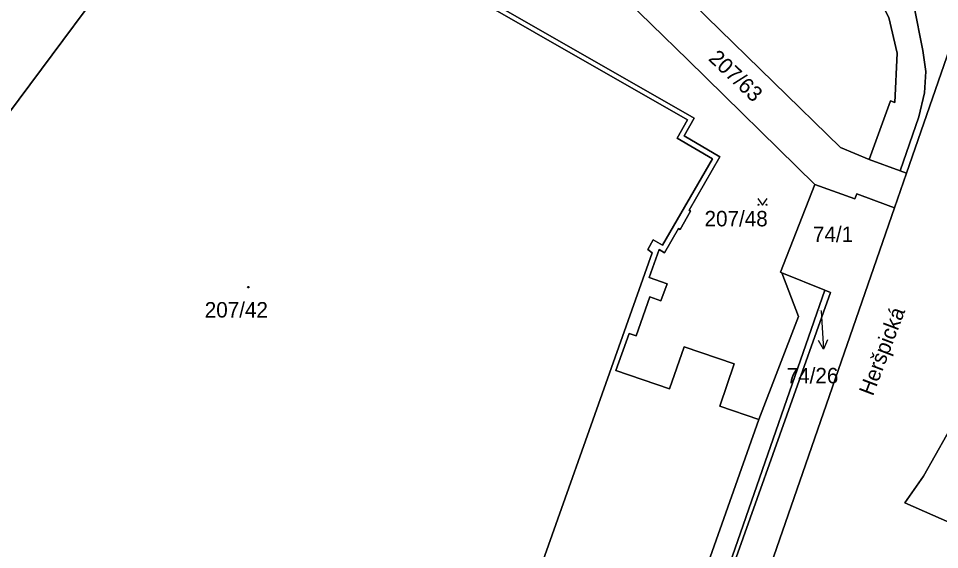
# Model space of a CAD drawing. Extents: x -598934 to -598196, y -1162208 to -1161502.
# Drawn here: x -598686.2 to -598584.8, y -1162112 to -1162053.5 of the extents above; entities that cross this region are included whole.
import ezdxf

# ---------------------------------------------------------------- set-up
doc = ezdxf.new("R2010")
doc.units = 0
for name, color, linetype in [('KN_KULTURY', 7, 'Continuous'), ('KN_PARC_CIS_POM', 7, 'Continuous'), ('KN_PARC_CIS_POZ', 7, 'Continuous'), ('KN_PARC_CIS_STAV', 7, 'Continuous'), ('KN_PARC_PLOCHA', 7, 'Continuous'), ('KN_ULICE', 7, 'Continuous'), ('PARC_C_SIPKA', 7, 'Continuous'), ('parcely_l', 7, 'Continuous')]:
    doc.layers.add(name, color=color, linetype=linetype)

msp = doc.modelspace()

# ---------------------------------------------------------------- linework, layer by layer
at = {"layer": 'KN_KULTURY'}
msp.add_lwpolyline([(-598604.79, -1162073.32), (-598604.29, -1162074.07), (-598603.79, -1162073.32)], dxfattribs=at)
for centre, radius in [((-598604.74, -1162074.02), 0.05), ((-598603.84, -1162074.02), 0.05), ((-598660.89, -1162083.09), 0.09), ((-598660.89, -1162083.09), 0.0398)]:
    msp.add_circle(centre, radius, dxfattribs=at)
at = {"layer": 'KN_PARC_PLOCHA'}
for points in [[(-598693.35, -1161970.89), (-598667.16, -1161993.18), (-598644.52, -1162009.55), (-598619.13, -1162024.88), (-598591.47, -1162039.7), (-598579.44, -1162044.4), (-598582.71, -1162054.06), (-598588.43, -1162070.55), (-598589.13, -1162070.29), (-598587.08, -1162064.36), (-598586.45, -1162061.72), (-598586.32, -1162059.38), (-598586.65, -1162057.07), (-598587.65, -1162052.06), (-598590.3, -1162047.38), (-598592.24, -1162045.35), (-598595.98, -1162042.57), (-598613.53, -1162032.97), (-598652.95, -1162008.48), (-598673.9, -1161993.31), (-598697.93, -1161974.03)], [(-598620.52, -1162050.28), (-598612.52, -1162058.09), (-598598.54, -1162071.79), (-598602.32, -1162081.45), (-598602.15, -1162081.52), (-598600.34, -1162086.32), (-598604.68, -1162097.65), (-598608.99, -1162096.19), (-598607.4, -1162091.53), (-598612.92, -1162089.65), (-598614.51, -1162094.26), (-598620.42, -1162092.27), (-598618.96, -1162088.18), (-598618.19, -1162088.45), (-598616.68, -1162084.17), (-598615.47, -1162084.6), (-598614.79, -1162082.74), (-598616.76, -1162082.02), (-598615.68, -1162078.96), (-598615.09, -1162079.3), (-598613.55, -1162076.63), (-598613.37, -1162076.73), (-598612.21, -1162074.73), (-598612.38, -1162074.63), (-598608.97, -1162068.74), (-598612.93, -1162066.44), (-598611.83, -1162064.5), (-598663.62, -1162034.85)], [(-598663.62, -1162034.85), (-598611.83, -1162064.5), (-598612.93, -1162066.44), (-598608.97, -1162068.74), (-598612.38, -1162074.63), (-598612.21, -1162074.73), (-598613.37, -1162076.73), (-598613.55, -1162076.63), (-598615.09, -1162079.3), (-598615.68, -1162078.96), (-598616.76, -1162082.02), (-598614.79, -1162082.74), (-598615.47, -1162084.6), (-598616.68, -1162084.17), (-598618.19, -1162088.45), (-598618.96, -1162088.18), (-598620.42, -1162092.27), (-598614.51, -1162094.26), (-598612.92, -1162089.65), (-598607.4, -1162091.53), (-598608.99, -1162096.19), (-598604.68, -1162097.65), (-598635.66, -1162185.2)], [(-598625.22, -1162038.92), (-598595.72, -1162067.74), (-598592.55, -1162069.05), (-598589.13, -1162070.29), (-598588.43, -1162070.55), (-598589.75, -1162074.37), (-598590.45, -1162074.11), (-598593.91, -1162072.84), (-598594.12, -1162073.38), (-598598.54, -1162071.79), (-598612.52, -1162058.09), (-598620.52, -1162050.28)], [(-598564.74, -1162050.65), (-598555.77, -1162053.54), (-598559.33, -1162063.57), (-598566.94, -1162060.47), (-598582.73, -1162097.08), (-598586.56, -1162103.9), (-598588.64, -1162106.82), (-598577.56, -1162111.7), (-598576.38, -1162112.22), (-598601.97, -1162185.82), (-598610.3, -1162192.29), (-598613.3, -1162200.15), (-598620.21, -1162196.02), (-598622.04, -1162194.78), (-598629.75, -1162189.23), (-598624.36, -1162173.57), (-598616.39, -1162151.12), (-598609.23, -1162130.49), (-598607.47, -1162125.48), (-598600.18, -1162104.44), (-598589.75, -1162074.37), (-598588.43, -1162070.55), (-598582.71, -1162054.06), (-598579.44, -1162044.4)], [(-598587.65, -1162052.06), (-598586.65, -1162057.07), (-598586.32, -1162059.38), (-598586.45, -1162061.72), (-598587.08, -1162064.36), (-598589.13, -1162070.29), (-598592.55, -1162069.05), (-598590.2, -1162062.59), (-598589.71, -1162062.79), (-598589.48, -1162057.35), (-598590.4, -1162053.41)]]:
    msp.add_lwpolyline(points, dxfattribs=at)
for points in [[(-598592.55, -1162069.05), (-598595.72, -1162067.74), (-598625.22, -1162038.92), (-598640.86, -1162023.52), (-598641.37, -1162022.35), (-598641.1, -1162021.73), (-598640.52, -1162021.18), (-598639.48, -1162020.74), (-598635.86, -1162023.09), (-598611.07, -1162037.77), (-598597.42, -1162045.2), (-598594.15, -1162047.66), (-598591.98, -1162050.31), (-598590.4, -1162053.41), (-598589.48, -1162057.35), (-598589.71, -1162062.79), (-598590.2, -1162062.59)], [(-598668.55, -1162035.34), (-598674.02, -1162044.9), (-598673, -1162045.47), (-598673.6, -1162046.51), (-598674.03, -1162046.15), (-598710.29, -1162094.83), (-598710.79, -1162094.46), (-598717.77, -1162103.75), (-598683.27, -1162115.94), (-598682.6, -1162114.05), (-598663.19, -1162120.99), (-598663.85, -1162122.86), (-598634.84, -1162133.15), (-598632.69, -1162127.23), (-598633.35, -1162126.99), (-598616.44, -1162079.32), (-598616.93, -1162078.93), (-598616.33, -1162077.89), (-598615.31, -1162078.48), (-598609.79, -1162068.96), (-598613.68, -1162066.69), (-598612.54, -1162064.68), (-598663.42, -1162035.55), (-598664.65, -1162037.57)], [(-598668.55, -1162035.34), (-598664.65, -1162037.57), (-598663.42, -1162035.55), (-598612.54, -1162064.68), (-598613.68, -1162066.69), (-598609.79, -1162068.96), (-598615.31, -1162078.48), (-598616.33, -1162077.89), (-598616.93, -1162078.93), (-598616.44, -1162079.32), (-598633.35, -1162126.99), (-598632.69, -1162127.23), (-598634.84, -1162133.15), (-598663.85, -1162122.86), (-598663.19, -1162120.99), (-598682.6, -1162114.05), (-598683.27, -1162115.94), (-598717.77, -1162103.75), (-598710.79, -1162094.46), (-598710.29, -1162094.83), (-598674.03, -1162046.15), (-598673.6, -1162046.51), (-598673, -1162045.47), (-598674.02, -1162044.9)], [(-598559.33, -1162063.57), (-598566.09, -1162082.63), (-598569.46, -1162092.03), (-598577.56, -1162111.7), (-598588.64, -1162106.82), (-598586.56, -1162103.9), (-598582.73, -1162097.08), (-598566.94, -1162060.47)], [(-598589.75, -1162074.37), (-598600.18, -1162104.44), (-598607.47, -1162125.48), (-598611.23, -1162124.16), (-598596.81, -1162083.67), (-598597.43, -1162083.42), (-598602.15, -1162081.52), (-598602.32, -1162081.45), (-598598.54, -1162071.79), (-598594.12, -1162073.38), (-598593.91, -1162072.84), (-598590.45, -1162074.11)], [(-598597.43, -1162083.42), (-598597.71, -1162084.28), (-598607.02, -1162110.95), (-598611.57, -1162124.04), (-598620.68, -1162150.69), (-598631.21, -1162180.12), (-598633.8, -1162185.51), (-598635.66, -1162185.2), (-598604.68, -1162097.65), (-598600.34, -1162086.32), (-598602.15, -1162081.52)], [(-598611.23, -1162124.16), (-598611.57, -1162124.04), (-598607.02, -1162110.95), (-598597.71, -1162084.28), (-598597.43, -1162083.42), (-598596.81, -1162083.67)]]:
    msp.add_lwpolyline(points, close=True, dxfattribs=at)
at = {"layer": 'PARC_C_SIPKA'}
for points in [[(-598597.85, -1162085.7), (-598597.77, -1162086.94), (-598597.58, -1162089.93)], [(-598597.15, -1162088.9), (-598597.58, -1162089.93), (-598598.14, -1162088.97)]]:
    msp.add_lwpolyline(points, dxfattribs=at)
at = {"layer": 'parcely_l'}
for points in [[(-598722.71, -1161953.41), (-598697.93, -1161974.03), (-598673.9, -1161993.31), (-598652.95, -1162008.48), (-598613.53, -1162032.97), (-598595.98, -1162042.57), (-598592.24, -1162045.35), (-598590.3, -1162047.38), (-598587.65, -1162052.06), (-598586.65, -1162057.07), (-598586.32, -1162059.38), (-598586.45, -1162061.72), (-598587.08, -1162064.36), (-598589.13, -1162070.29)], [(-598592.55, -1162069.05), (-598595.72, -1162067.74), (-598625.22, -1162038.92), (-598640.86, -1162023.52), (-598641.37, -1162022.35), (-598641.1, -1162021.73), (-598640.52, -1162021.18), (-598639.48, -1162020.74)], [(-598592.55, -1162069.05), (-598590.2, -1162062.59), (-598589.71, -1162062.79), (-598589.48, -1162057.35), (-598590.4, -1162053.41), (-598591.98, -1162050.31), (-598594.15, -1162047.66), (-598597.42, -1162045.2), (-598611.07, -1162037.77), (-598635.86, -1162023.09), (-598639.48, -1162020.74)], [(-598668.55, -1162035.34), (-598664.65, -1162037.57), (-598663.42, -1162035.55), (-598612.54, -1162064.68), (-598613.68, -1162066.69), (-598609.79, -1162068.96), (-598615.31, -1162078.48), (-598616.33, -1162077.89), (-598616.93, -1162078.93), (-598616.44, -1162079.32), (-598633.35, -1162126.99), (-598632.69, -1162127.23), (-598634.84, -1162133.15), (-598663.85, -1162122.86), (-598663.19, -1162120.99), (-598682.6, -1162114.05), (-598683.27, -1162115.94), (-598717.77, -1162103.75)], [(-598710.29, -1162094.83), (-598674.03, -1162046.15), (-598673.6, -1162046.51), (-598673, -1162045.47), (-598674.02, -1162044.9), (-598668.55, -1162035.34)], [(-598663.62, -1162034.85), (-598611.83, -1162064.5), (-598612.93, -1162066.44), (-598608.97, -1162068.74), (-598612.38, -1162074.63), (-598612.21, -1162074.73), (-598613.37, -1162076.73), (-598613.55, -1162076.63), (-598615.09, -1162079.3), (-598615.68, -1162078.96), (-598616.76, -1162082.02), (-598614.79, -1162082.74), (-598615.47, -1162084.6), (-598616.68, -1162084.17), (-598618.19, -1162088.45), (-598618.96, -1162088.18), (-598620.42, -1162092.27), (-598614.51, -1162094.26), (-598612.92, -1162089.65), (-598607.4, -1162091.53), (-598608.99, -1162096.19), (-598604.68, -1162097.65)], [(-598588.43, -1162070.55), (-598582.71, -1162054.06), (-598579.44, -1162044.4)], [(-598598.54, -1162071.79), (-598612.52, -1162058.09), (-598620.52, -1162050.28)], [(-598559.33, -1162063.57), (-598566.94, -1162060.47), (-598582.73, -1162097.08), (-598586.56, -1162103.9), (-598588.64, -1162106.82), (-598577.56, -1162111.7)], [(-598589.13, -1162070.29), (-598592.55, -1162069.05)], [(-598589.75, -1162074.37), (-598588.43, -1162070.55)], [(-598588.43, -1162070.55), (-598589.13, -1162070.29)], [(-598602.15, -1162081.52), (-598602.32, -1162081.45), (-598598.54, -1162071.79)], [(-598598.54, -1162071.79), (-598594.12, -1162073.38), (-598593.91, -1162072.84), (-598590.45, -1162074.11), (-598589.75, -1162074.37)], [(-598607.47, -1162125.48), (-598600.18, -1162104.44), (-598589.75, -1162074.37)], [(-598604.68, -1162097.65), (-598600.34, -1162086.32), (-598602.15, -1162081.52)], [(-598597.43, -1162083.42), (-598602.15, -1162081.52)], [(-598611.57, -1162124.04), (-598607.02, -1162110.95), (-598597.71, -1162084.28), (-598597.43, -1162083.42)], [(-598597.43, -1162083.42), (-598596.81, -1162083.67), (-598611.23, -1162124.16)], [(-598604.68, -1162097.65), (-598635.66, -1162185.2)]]:
    msp.add_lwpolyline(points, dxfattribs=at)

# ---------------------------------------------------------------- texts
at = {"layer": 'KN_PARC_CIS_POM'}
msp.add_text('74/26', height=0.1, dxfattribs=at).set_placement((-598598.08, -1162085.7))
at = {"layer": 'KN_PARC_CIS_POZ'}
msp.add_text('207/63', height=1.7, rotation=316.5, dxfattribs=at).set_placement((-598610.33, -1162058.05))
for s, p in [('207/48', (-598610.67, -1162076.4)), ('74/1', (-598598.74, -1162078.12)), ('74/26', (-598601.63, -1162093.67))]:
    msp.add_text(s, height=1.7, dxfattribs=at).set_placement(p)
at = {"layer": 'KN_PARC_CIS_STAV'}
msp.add_text('207/42', height=1.7, dxfattribs=at).set_placement((-598665.68, -1162086.43))
at = {"layer": 'KN_ULICE'}
msp.add_text('Heršpická', height=1.7, rotation=69.2998, dxfattribs=at).set_placement((-598592.14, -1162095.15))

doc.saveas('drawing.dxf')
